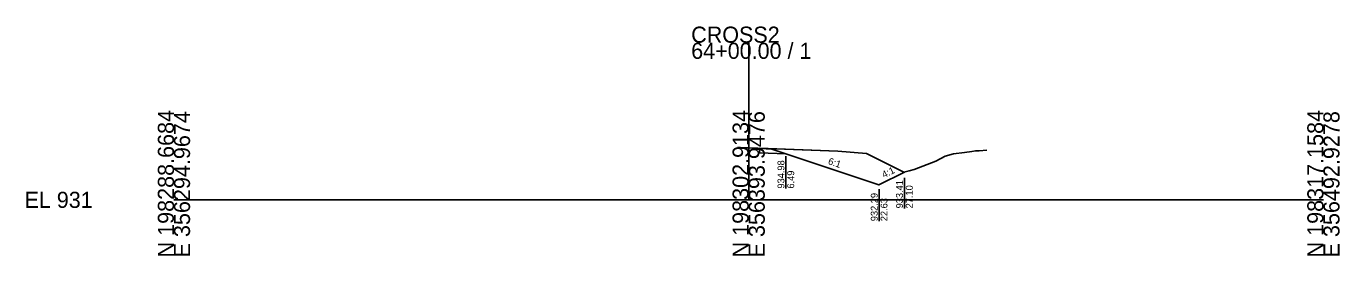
# Model space of a CAD drawing. Extents: x -26 to 203, y -10 to 14021.
# Drawn here: x -25.7 to 202.8, y 4990.3 to 5030.1 of the extents above; entities that cross this region are included whole.
import ezdxf

# ---------------------------------------------------------------- set-up
doc = ezdxf.new("R2010")
doc.units = 0
for name, color, linetype in [('Default', 7, 'Continuous'), ('P_E_XS_Ground', 7, 'Continuous'), ('P_XS', 7, 'Continuous'), ('P_XS_EAR_CommonGrnd', 7, 'Continuous'), ('P_XS_Lane', 7, 'Continuous'), ('P_XS_Rock', 7, 'Continuous')]:
    doc.layers.add(name, color=color, linetype=linetype)

msp = doc.modelspace()

# ---------------------------------------------------------------- linework, layer by layer
at = {"layer": 'Default'}
for p, q in [((100, 5000), (100, 5027.28)), ((0, 5000), (100, 5000)), ((100, 5000), (200, 5000))]:
    msp.add_line(p, q, dxfattribs=at)
at = {"layer": 'P_E_XS_Ground'}
for p, q in [((98.04, 5009.09), (98.58, 5009.08)), ((100, 5009.05), (98.58, 5009.11)), ((98.58, 5009.11), (98.58, 5009.08)), ((115.5, 5008.43), (100, 5009.05)), ((115.5, 5008.43), (120.5, 5008.03)), ((120.5, 5008.03), (126.99, 5004.79)), ((132.55, 5006.74), (134.17, 5007.56)), ((134.17, 5007.56), (135.62, 5007.98)), ((135.62, 5007.98), (137.57, 5008.2)), ((137.57, 5008.2), (138.83, 5008.39)), ((138.83, 5008.39), (139.48, 5008.5)), ((139.48, 5008.5), (140.08, 5008.51)), ((140.08, 5008.51), (141.46, 5008.62)), ((126.99, 5004.79), (127.94, 5005.03)), ((127.94, 5005.03), (128.77, 5005.28)), ((128.77, 5005.28), (132.55, 5006.74))]:
    msp.add_line(p, q, dxfattribs=at)
at = {"layer": 'P_XS'}
for p, q in [((98.04, 5009.09), (102.04, 5008.93)), ((102.04, 5008.93), (104.04, 5008.77)), ((106.49, 5007.96), (104.04, 5008.77))]:
    msp.add_line(p, q, dxfattribs=at)
at = {"layer": 'P_XS_EAR_CommonGrnd'}
msp.add_lwpolyline([(115.5, 5008.43), (101.91, 5008.98), (101.91, 5008.14), (106.49, 5007.96), (122.63, 5002.58), (127.1, 5004.82), (126.99, 5004.79), (120.5, 5008.03)], close=True, dxfattribs=at)
at = {"layer": 'P_XS_Lane'}
for p, q in [((101.91, 5008.98), (101.91, 5008.14)), ((106.49, 5007.96), (101.91, 5008.14)), ((122.63, 5002.58), (106.49, 5007.96)), ((122.63, 5002.58), (127.1, 5004.82))]:
    msp.add_line(p, q, dxfattribs=at)
at = {"layer": 'P_XS_Rock'}
for p, q in [((106.47, 5007.58), (106.47, 5001.96)), ((127.09, 5003.81), (127.09, 4998.51)), ((122.7, 5001.88), (122.7, 4996.29))]:
    msp.add_line(p, q, dxfattribs=at)

# ---------------------------------------------------------------- texts
at = {"layer": 'Default'}
for s, p in [('CROSS2', (90, 5027.28)), ('64+00.00 / 1', (90, 5024.48)), ('EL 931', (-26, 4998.6))]:
    msp.add_text(s, height=2.8, dxfattribs=at).set_placement(p)
for s, p in [('N 198288.6684', (0, 4990)), ('E 356294.9674', (2.8, 4990)), ('N 198302.9134', (100, 4990)), ('E 356393.9476', (102.8, 4990)), ('N 198317.1584', (200, 4990)), ('E 356492.9278', (202.8, 4990))]:
    msp.add_text(s, height=2.8, rotation=90, dxfattribs=at).set_placement(p)
at = {"layer": 'P_XS_Rock'}
for s, rotation, p in [('6:1', 341.5651, (113.72, 5006.23)), ('934.98', 90, (106.22, 5001.96)), ('6.49', 90, (107.92, 5001.96)), ('4:1', 26.5651, (123.55, 5003.74)), ('933.41', 90, (126.84, 4998.52)), ('932.29', 90, (122.45, 4996.29)), ('27.10', 90, (128.54, 4998.52)), ('22.63', 90, (124.15, 4996.29))]:
    msp.add_text(s, height=1.2, rotation=rotation, dxfattribs=at).set_placement(p)

doc.saveas('drawing.dxf')
